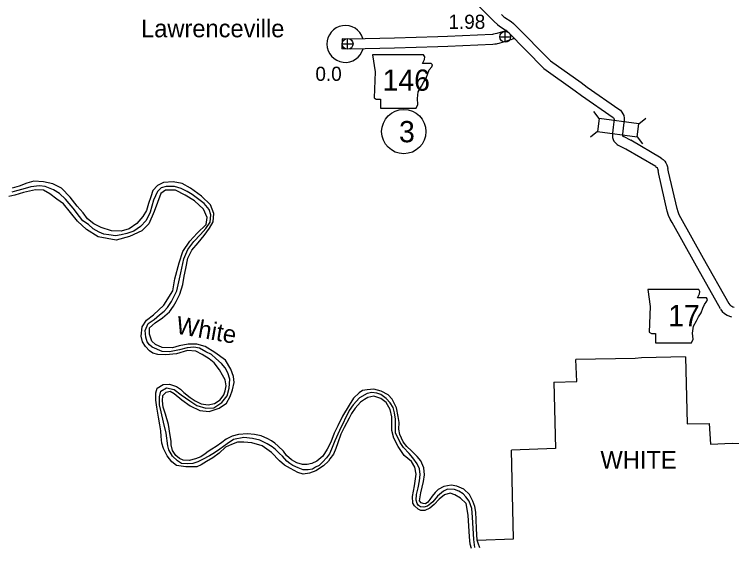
# Model space of a CAD drawing. Extents: x -939622 to -934222, y 1383701 to 1385301.
# Drawn here: x -935986.8 to -935922.6, y 1383989.8 to 1384037.4 of the extents above; entities that cross this region are included whole.
import ezdxf

# ---------------------------------------------------------------- set-up
doc = ezdxf.new("R2010")
doc.units = 0
for name, color, linetype in [('Level 10', 7, 'Continuous'), ('Level 2', 7, 'Continuous'), ('Level 20', 7, 'Continuous'), ('Level 21', 7, 'Continuous'), ('Level 24', 7, 'Continuous'), ('Level 25', 7, 'Continuous'), ('Level 26', 7, 'Continuous'), ('Level 27', 7, 'Continuous'), ('Level 7', 7, 'Continuous'), ('Level 9', 7, 'Continuous')]:
    doc.layers.add(name, color=color, linetype=linetype)

msp = doc.modelspace()

# ---------------------------------------------------------------- linework, layer by layer
at = {"layer": 'Level 10'}
for points in [[(-935954.97, 1384050.035), (-935949.402, 1384043.116), (-935945.476, 1384038.46), (-935943.829, 1384036.81)], [(-935943.19, 1384037.445), (-935942.968, 1384037.219), (-935942.873, 1384037.154), (-935942.317, 1384036.805), (-935942.097, 1384036.629), (-935941.939, 1384036.464)], [(-935943.831, 1384036.812), (-935943.549, 1384036.527), (-935943.368, 1384036.402), (-935942.839, 1384036.07), (-935942.705, 1384035.963), (-935942.589, 1384035.841)], [(-935941.944, 1384036.469), (-935938.802, 1384033.284), (-935936.059, 1384031.336), (-935935.494, 1384030.92)], [(-935942.718, 1384035.997), (-935942.885, 1384035.954), (-935943.605, 1384035.718), (-935943.753, 1384035.7), (-935943.864, 1384035.668), (-935943.893, 1384035.663), (-935943.997, 1384035.656), (-935948.008, 1384035.454), (-935948.884, 1384035.438), (-935952.767, 1384035.325), (-935956.69, 1384035.233), (-935957.434, 1384035.254)], [(-935942.585, 1384035.837), (-935939.388, 1384032.596), (-935936.587, 1384030.606), (-935936.027, 1384030.195)], [(-935942.036, 1384035.267), (-935942.097, 1384035.256), (-935942.126, 1384035.247), (-935942.223, 1384035.211), (-935942.266, 1384035.2), (-935942.329, 1384035.167), (-935942.47, 1384035.131), (-935942.634, 1384035.089), (-935943.411, 1384034.834), (-935943.573, 1384034.815), (-935943.659, 1384034.79), (-935943.786, 1384034.768), (-935943.946, 1384034.758), (-935947.977, 1384034.555), (-935948.863, 1384034.538), (-935952.743, 1384034.425), (-935956.692, 1384034.333), (-935957.46, 1384034.355)], [(-935957.434, 1384035.254), (-935957.46, 1384034.355)], [(-935935.505, 1384030.928), (-935932.665, 1384028.969)], [(-935936.016, 1384030.187), (-935933.176, 1384028.228)], [(-935932.665, 1384028.969), (-935932.533, 1384028.86), (-935932.399, 1384028.703), (-935932.315, 1384028.555), (-935932.232, 1384028.396), (-935932.185, 1384028.165), (-935932.189, 1384027.993)], [(-935933.085, 1384028.062), (-935933.177, 1384027.362), (-935933.242, 1384026.822)], [(-935933.212, 1384028.256), (-935933.171, 1384028.221), (-935933.139, 1384028.183), (-935933.106, 1384028.125), (-935933.089, 1384028.093), (-935933.087, 1384028.083), (-935933.088, 1384028.014)], [(-935932.189, 1384027.993), (-935932.284, 1384027.249), (-935932.348, 1384026.715)], [(-935933.245, 1384026.792), (-935933.253, 1384026.623), (-935933.237, 1384026.436), (-935933.194, 1384026.248), (-935933.108, 1384026.098), (-935933.011, 1384025.966), (-935932.912, 1384025.874), (-935932.812, 1384025.799), (-935932.735, 1384025.751)], [(-935932.346, 1384026.745), (-935932.351, 1384026.638), (-935932.346, 1384026.582), (-935932.335, 1384026.566), (-935932.334, 1384026.565), (-935932.307, 1384026.545), (-935932.266, 1384026.52)], [(-935932.294, 1384026.536), (-935931.6, 1384026.177)], [(-935928.873, 1384024.574), (-935931.6, 1384026.177)], [(-935932.735, 1384025.751), (-935932.013, 1384025.378)], [(-935929.362, 1384023.82), (-935932.034, 1384025.39)], [(-935928.873, 1384024.574), (-935928.716, 1384024.462), (-935928.564, 1384024.316), (-935928.45, 1384024.151), (-935928.367, 1384023.974), (-935928.311, 1384023.797), (-935928.279, 1384023.664)], [(-935929.396, 1384023.842), (-935929.293, 1384023.768), (-935929.254, 1384023.73), (-935929.233, 1384023.701), (-935929.207, 1384023.644), (-935929.178, 1384023.555), (-935929.154, 1384023.454)], [(-935922.795, 1384011.543), (-935925.089, 1384015.606), (-935927.119, 1384019.249), (-935927.256, 1384019.514), (-935927.37, 1384019.77), (-935927.464, 1384020.059), (-935928.211, 1384023.351), (-935928.277, 1384023.654)], [(-935923.579, 1384011.101), (-935925.874, 1384015.166), (-935927.911, 1384018.823), (-935928.067, 1384019.124), (-935928.211, 1384019.447), (-935928.332, 1384019.82), (-935929.089, 1384023.156), (-935929.156, 1384023.463)], [(-935922.811, 1384011.569), (-935922.728, 1384011.442), (-935922.667, 1384011.388), (-935922.563, 1384011.321), (-935922.48, 1384011.288), (-935922.354, 1384011.256)], [(-935923.563, 1384011.075), (-935923.415, 1384010.849), (-935923.214, 1384010.67), (-935922.977, 1384010.517), (-935922.756, 1384010.43), (-935922.574, 1384010.384)]]:
    msp.add_lwpolyline(points, dxfattribs=at)
at = {"layer": 'Level 2'}
for points in [[(-935969.203, 1384019.514), (-935969.342, 1384019.983), (-935969.799, 1384020.511), (-935970.403, 1384020.982), (-935970.878, 1384021.318), (-935971.313, 1384021.605), (-935971.868, 1384021.853), (-935972.438, 1384022.05), (-935973.199, 1384022.051), (-935973.633, 1384021.924), (-935973.976, 1384021.586), (-935974.321, 1384020.824), (-935974.638, 1384019.759), (-935974.982, 1384019.012), (-935975.499, 1384018.452), (-935976.099, 1384018.032), (-935976.725, 1384017.829), (-935977.222, 1384017.713), (-935977.73, 1384017.619), (-935978.324, 1384017.708), (-935978.773, 1384017.782), (-935979.205, 1384017.964), (-935979.737, 1384018.254), (-935980.16, 1384018.647), (-935980.656, 1384018.983), (-935980.957, 1384019.364), (-935981.526, 1384020.108), (-935981.88, 1384020.534), (-935982.217, 1384020.909), (-935982.755, 1384021.419), (-935983.275, 1384021.74), (-935984.033, 1384022.03), (-935984.552, 1384022.115), (-935985.322, 1384022.02), (-935986.037, 1384021.814), (-935986.602, 1384021.65), (-935987.015, 1384021.532)], [(-935952.656, 1383999.955), (-935952.667, 1384000.382), (-935952.657, 1384001.212), (-935952.743, 1384001.781), (-935952.871, 1384002.273), (-935953.13, 1384002.682), (-935953.503, 1384003.063), (-935953.968, 1384003.422), (-935954.331, 1384003.554), (-935954.79, 1384003.598), (-935955.209, 1384003.521), (-935955.887, 1384003.123), (-935956.448, 1384002.49), (-935956.815, 1384002.002), (-935957.684, 1384000.213), (-935958.094, 1383999.295), (-935958.391, 1383998.551), (-935958.563, 1383998.106), (-935958.84, 1383997.759), (-935959.166, 1383997.397), (-935959.506, 1383997.081), (-935959.814, 1383996.912), (-935960.107, 1383996.736), (-935960.475, 1383996.684), (-935960.933, 1383996.701), (-935961.392, 1383996.856), (-935961.845, 1383997.075), (-935962.131, 1383997.26), (-935962.395, 1383997.464), (-935962.786, 1383997.896), (-935963.053, 1383998.151), (-935963.399, 1383998.502), (-935963.7, 1383998.751), (-935964.147, 1383999.003), (-935964.819, 1383999.344), (-935965.481, 1383999.492), (-935966.246, 1383999.569), (-935967.174, 1383999.398), (-935967.732, 1383999.017), (-935968.408, 1383998.546), (-935968.883, 1383998.205), (-935969.328, 1383997.934), (-935969.953, 1383997.598), (-935970.366, 1383997.417), (-935970.806, 1383997.262), (-935971.312, 1383997.21), (-935971.839, 1383997.266), (-935972.17, 1383997.502), (-935972.623, 1383997.916), (-935972.955, 1383998.49), (-935973.052, 1383998.826), (-935973.212, 1383999.975), (-935973.44, 1384000.966), (-935973.653, 1384001.889), (-935973.787, 1384002.511), (-935973.798, 1384003.224), (-935973.677, 1384003.718), (-935973.154, 1384004.02), (-935972.479, 1384003.88), (-935971.864, 1384003.394), (-935971.083, 1384002.858), (-935970.44, 1384002.43), (-935969.652, 1384002.203), (-935968.939, 1384002.223), (-935968.225, 1384002.7), (-935967.75, 1384003.318), (-935967.552, 1384003.992), (-935967.507, 1384004.786), (-935967.686, 1384005.375), (-935967.924, 1384005.819), (-935968.258, 1384006.2), (-935968.745, 1384006.647), (-935969.141, 1384007.004), (-935969.636, 1384007.246), (-935970.228, 1384007.561), (-935970.734, 1384007.662), (-935971.33, 1384007.609), (-935972.003, 1384007.427), (-935972.895, 1384007.244), (-935973.567, 1384007.266), (-935974.455, 1384007.673), (-935974.698, 1384007.874), (-935974.897, 1384008.147), (-935975.018, 1384008.547), (-935975.086, 1384009.142), (-935974.812, 1384009.768), (-935974.275, 1384010.143), (-935973.788, 1384010.544), (-935973.384, 1384010.9), (-935973.08, 1384011.204), (-935972.713, 1384011.75), (-935972.246, 1384012.692), (-935972.055, 1384013.505), (-935971.896, 1384014.329), (-935971.612, 1384015.566), (-935971.259, 1384016.415), (-935970.713, 1384017.117), (-935970.119, 1384017.75), (-935969.642, 1384018.286), (-935969.245, 1384018.838), (-935969.203, 1384019.514)], [(-935945.575, 1383989.725), (-935945.655, 1383990.458), (-935945.782, 1383992.446), (-935945.842, 1383993.236), (-935946.084, 1383993.891), (-935946.373, 1383994.261), (-935946.616, 1383994.531), (-935946.994, 1383994.764), (-935947.393, 1383994.932), (-935948.008, 1383994.963), (-935948.357, 1383994.788), (-935948.898, 1383994.317), (-935949.328, 1383993.814), (-935949.507, 1383993.66), (-935949.791, 1383993.437), (-935950.126, 1383993.34), (-935950.414, 1383993.384), (-935950.597, 1383993.492), (-935950.72, 1383993.678), (-935950.811, 1383993.975), (-935950.78, 1383994.478), (-935950.647, 1383995.071), (-935950.52, 1383995.699), (-935950.451, 1383996.28), (-935950.506, 1383996.77), (-935950.72, 1383997.218), (-935951.103, 1383997.77), (-935951.443, 1383998.148), (-935951.963, 1383998.694), (-935952.246, 1383999.135), (-935952.472, 1383999.592), (-935952.656, 1383999.955)]]:
    msp.add_lwpolyline(points, dxfattribs=at)
at = {"layer": 'Level 20'}
for p, q in [((-935934.42, 1384028.128), (-935934.901, 1384028.756)), ((-935930.886, 1384027.661), (-935930.258, 1384028.143)), ((-935934.575, 1384026.95), (-935935.204, 1384026.468)), ((-935931.042, 1384026.483), (-935930.56, 1384025.855))]:
    msp.add_line(p, q, dxfattribs=at)
msp.add_lwpolyline([(-935930.886, 1384027.661), (-935934.42, 1384028.128), (-935934.575, 1384026.95), (-935931.042, 1384026.483)], close=True, dxfattribs=at)
at = {"layer": 'Level 21'}
for points in [[(-935954.714, 1384033.822), (-935954.486, 1384032.299), (-935954.588, 1384029.99), (-935954.384, 1384029.863), (-935954.004, 1384029.863), (-935954.004, 1384029.051), (-935950.806, 1384029.051), (-935950.654, 1384029.381), (-935950.705, 1384029.914), (-935950.629, 1384030.523), (-935950.35, 1384031.005), (-935950.172, 1384031.361), (-935949.918, 1384031.741), (-935949.766, 1384032.147), (-935949.639, 1384032.477), (-935949.411, 1384032.756), (-935949.36, 1384032.934), (-935949.461, 1384033.061), (-935950.248, 1384033.061), (-935950.07, 1384033.416), (-935950.045, 1384033.644), (-935950.15, 1384033.82)], [(-935930.088, 1384012.832), (-935929.859, 1384011.309), (-935929.961, 1384009), (-935929.758, 1384008.873), (-935929.377, 1384008.873), (-935929.377, 1384008.061), (-935926.18, 1384008.061), (-935926.028, 1384008.391), (-935926.078, 1384008.924), (-935926.002, 1384009.533), (-935925.723, 1384010.015), (-935925.545, 1384010.37), (-935925.292, 1384010.751), (-935925.139, 1384011.157), (-935925.012, 1384011.487), (-935924.784, 1384011.766), (-935924.733, 1384011.944), (-935924.835, 1384012.071), (-935925.622, 1384012.071), (-935925.444, 1384012.426), (-935925.419, 1384012.654), (-935925.524, 1384012.83)]]:
    msp.add_lwpolyline(points, close=True, dxfattribs=at)
at = {"layer": 'Level 24'}
msp.add_arc((-935957.157, 1384034.797), 1.65, 17.41887, 344.76747, dxfattribs=at)
at = {"layer": 'Level 26'}
for p, q in [((-935942.847, 1384034.946), (-935942.847, 1384035.921)), ((-935956.953, 1384034.319), (-935956.953, 1384035.294)), ((-935943.335, 1384035.434), (-935942.36, 1384035.434)), ((-935957.441, 1384034.806), (-935956.466, 1384034.806))]:
    msp.add_line(p, q, dxfattribs=at)
for centre in [(-935942.847, 1384035.434), (-935956.953, 1384034.806)]:
    msp.add_circle(centre, 0.487, dxfattribs=at)
at = {"layer": 'Level 27'}
msp.add_circle((-935951.927, 1384026.95), 1.98, dxfattribs=at)
at = {"layer": 'Level 7'}
for points in [[(-935926.715, 1384006.802), (-935930.656, 1384006.695), (-935931.214, 1384006.658)], [(-935926.715, 1384006.802), (-935926.558, 1384000.8), (-935924.586, 1384000.846)], [(-935938.477, 1384004.526), (-935936.437, 1384004.59), (-935936.536, 1384006.546)], [(-935931.214, 1384006.658), (-935936.536, 1384006.546)], [(-935938.477, 1384004.526), (-935938.339, 1383998.586)], [(-935924.586, 1384000.846), (-935924.477, 1383998.989), (-935922.526, 1383999.065), (-935920.519, 1383998.99), (-935920.455, 1383997.019)], [(-935945.362, 1383990.408), (-935942.097, 1383990.503), (-935942.278, 1383998.457)], [(-935938.339, 1383998.586), (-935942.278, 1383998.457)]]:
    msp.add_lwpolyline(points, dxfattribs=at)
at = {"layer": 'Level 9'}
for points in [[(-935971.765, 1384022.296), (-935972.586, 1384022.447), (-935973.445, 1384022.385), (-935973.975, 1384022.134), (-935974.381, 1384021.684), (-935974.579, 1384021.125), (-935974.766, 1384020.526), (-935974.947, 1384019.9), (-935975.289, 1384019.351), (-935975.817, 1384018.725), (-935976.501, 1384018.242), (-935977.238, 1384018.05), (-935978.088, 1384018.063), (-935979.018, 1384018.367), (-935979.666, 1384018.712), (-935980.243, 1384019.146), (-935980.637, 1384019.671), (-935981.179, 1384020.272), (-935981.799, 1384021.082), (-935982.562, 1384021.898), (-935983.354, 1384022.278), (-935984.179, 1384022.471), (-935985.045, 1384022.511), (-935985.682, 1384022.341), (-935986.349, 1384022.072), (-935986.984, 1384021.89)], [(-935952.425, 1384001.448), (-935952.568, 1384002.223), (-935952.963, 1384002.998), (-935953.312, 1384003.397), (-935953.957, 1384003.723), (-935954.614, 1384003.914), (-935955.195, 1384003.855), (-935955.611, 1384003.773), (-935955.916, 1384003.571), (-935956.426, 1384003.1), (-935956.823, 1384002.474), (-935957.424, 1384001.504), (-935957.844, 1384000.631), (-935958.165, 1383999.959), (-935958.468, 1383999.149), (-935958.783, 1383998.529), (-935959.173, 1383997.897), (-935959.705, 1383997.459), (-935960.145, 1383997.244), (-935960.567, 1383997.159), (-935960.998, 1383997.164), (-935961.514, 1383997.307), (-935961.97, 1383997.577), (-935962.424, 1383997.963), (-935962.683, 1383998.36), (-935963.167, 1383998.819), (-935963.476, 1383999.07), (-935963.755, 1383999.292), (-935964.106, 1383999.475), (-935964.694, 1383999.732), (-935965.282, 1383999.86), (-935965.908, 1383999.909), (-935966.711, 1383999.859), (-935967.303, 1383999.686), (-935967.812, 1383999.42), (-935968.212, 1383999.127), (-935968.726, 1383998.762), (-935969.097, 1383998.539), (-935969.45, 1383998.327), (-935969.721, 1383998.113), (-935970.107, 1383997.853), (-935970.585, 1383997.657), (-935971.133, 1383997.52), (-935971.669, 1383997.543), (-935972.006, 1383997.698), (-935972.327, 1383997.98), (-935972.616, 1383998.427), (-935972.741, 1383998.914), (-935972.76, 1383999.26), (-935972.836, 1383999.765), (-935972.981, 1384000.739), (-935973.259, 1384001.659), (-935973.453, 1384002.305), (-935973.527, 1384002.864), (-935973.511, 1384003.324), (-935973.203, 1384003.65), (-935972.853, 1384003.741), (-935972.49, 1384003.513), (-935971.808, 1384002.961), (-935971.063, 1384002.401), (-935970.172, 1384002.009), (-935969.348, 1384001.9), (-935968.457, 1384002.206), (-935967.796, 1384002.641), (-935967.46, 1384003.246), (-935967.246, 1384003.842), (-935967.113, 1384004.489), (-935967.169, 1384005.03), (-935967.402, 1384005.7), (-935967.884, 1384006.499), (-935968.83, 1384007.188), (-935969.71, 1384007.736), (-935970.457, 1384007.939), (-935971.235, 1384007.937), (-935972.023, 1384007.776), (-935972.63, 1384007.618), (-935973.553, 1384007.636), (-935974.15, 1384007.893), (-935974.478, 1384008.211), (-935974.683, 1384008.833), (-935974.688, 1384009.396), (-935974.193, 1384009.851), (-935973.514, 1384010.283), (-935972.905, 1384010.838), (-935972.544, 1384011.323), (-935972.294, 1384011.751), (-935971.961, 1384012.407), (-935971.694, 1384013.277), (-935971.592, 1384014.008), (-935971.448, 1384014.709), (-935971.271, 1384015.642), (-935970.896, 1384016.358), (-935970.344, 1384017.012), (-935969.792, 1384017.663), (-935969.306, 1384018.311), (-935969, 1384018.874), (-935968.945, 1384019.611), (-935969.233, 1384020.386), (-935970.044, 1384021.178), (-935971.008, 1384021.886), (-935971.765, 1384022.296)], [(-935969.622, 1384018.629), (-935969.516, 1384019.27), (-935969.846, 1384020.018), (-935970.675, 1384020.756), (-935971.509, 1384021.28), (-935972.362, 1384021.723), (-935973.266, 1384021.702), (-935973.688, 1384021.416), (-935974.269, 1384019.808), (-935974.739, 1384018.7), (-935975.372, 1384018.076), (-935976.481, 1384017.568), (-935977.666, 1384017.249), (-935979.276, 1384017.546), (-935980.345, 1384018.205), (-935981.138, 1384018.948), (-935982.378, 1384020.482), (-935982.975, 1384020.904), (-935983.615, 1384021.378), (-935984.182, 1384021.704), (-935984.889, 1384021.736), (-935985.985, 1384021.504), (-935986.742, 1384021.259), (-935987.296, 1384021.152)], [(-935950.831, 1383996.3), (-935950.929, 1383996.928), (-935951.227, 1383997.424), (-935951.903, 1383997.984), (-935952.424, 1383998.786), (-935952.825, 1383999.531), (-935952.993, 1384000.216), (-935952.986, 1384000.902), (-935952.994, 1384001.428), (-935953.143, 1384002.08), (-935953.498, 1384002.72), (-935953.988, 1384003.082), (-935954.606, 1384003.267), (-935955.13, 1384003.161), (-935955.449, 1384002.973), (-935955.796, 1384002.75), (-935956.283, 1384002.216), (-935956.595, 1384001.741), (-935956.828, 1384001.301), (-935957.265, 1384000.482), (-935957.548, 1383999.871), (-935957.841, 1383999.109), (-935958.022, 1383998.594), (-935958.227, 1383998.076), (-935958.534, 1383997.664), (-935958.663, 1383997.477), (-935959.101, 1383997.04), (-935959.786, 1383996.59), (-935960.351, 1383996.384), (-935960.944, 1383996.304), (-935961.406, 1383996.453), (-935962.063, 1383996.794), (-935962.597, 1383997.097), (-935963.048, 1383997.502), (-935963.773, 1383998.243), (-935964.592, 1383998.827), (-935965.534, 1383999.107), (-935966.244, 1383999.15), (-935966.81, 1383999.17), (-935967.346, 1383998.952), (-935967.872, 1383998.716), (-935968.46, 1383998.188), (-935969.013, 1383997.772), (-935969.59, 1383997.419), (-935970.068, 1383997.132), (-935970.457, 1383996.968), (-935971.428, 1383996.966), (-935972.258, 1383997.066), (-935972.697, 1383997.417), (-935973.094, 1383997.942), (-935973.426, 1383998.606), (-935973.574, 1383999.087), (-935973.636, 1383999.664), (-935973.668, 1384000.175), (-935973.753, 1384000.719), (-935973.894, 1384001.386), (-935974.047, 1384002.291), (-935974.124, 1384002.913), (-935974.126, 1384003.572), (-935973.996, 1384004.005), (-935973.469, 1384004.314), (-935972.888, 1384004.339), (-935972.28, 1384004.136), (-935971.904, 1384003.891), (-935971.604, 1384003.612), (-935971.063, 1384003.153), (-935970.592, 1384002.853), (-935970.055, 1384002.599), (-935969.434, 1384002.507), (-935968.874, 1384002.611), (-935968.375, 1384002.961), (-935968.041, 1384003.407), (-935967.92, 1384003.768), (-935967.84, 1384004.196), (-935967.923, 1384004.755), (-935968.14, 1384005.151), (-935968.43, 1384005.641), (-935968.908, 1384006.25), (-935969.359, 1384006.631), (-935969.986, 1384007.011), (-935970.532, 1384007.298), (-935971.278, 1384007.375), (-935972.281, 1384007.071), (-935973.227, 1384006.988), (-935973.949, 1384006.995), (-935974.402, 1384007.138), (-935974.681, 1384007.345), (-935975.063, 1384007.723), (-935975.316, 1384008.134), (-935975.444, 1384008.663), (-935975.339, 1384009.478), (-935974.963, 1384010.075), (-935974.336, 1384010.57), (-935973.395, 1384011.414), (-935972.591, 1384012.703), (-935972.436, 1384013.777), (-935972.022, 1384015.225), (-935971.716, 1384016.215), (-935971.067, 1384017.161), (-935970.431, 1384017.857), (-935969.622, 1384018.629)], [(-935945.129, 1383989.705), (-935945.253, 1383990.119), (-935945.362, 1383990.408), (-935945.413, 1383991.421), (-935945.434, 1383992.251), (-935945.475, 1383992.904), (-935945.576, 1383993.4), (-935945.742, 1383993.895), (-935946.044, 1383994.466), (-935946.561, 1383994.946), (-935947.161, 1383995.227), (-935947.697, 1383995.322), (-935948.341, 1383995.194), (-935948.861, 1383994.919), (-935949.13, 1383994.668), (-935949.371, 1383994.325), (-935949.598, 1383994.021), (-935949.762, 1383993.792), (-935949.995, 1383993.641), (-935950.196, 1383993.664), (-935950.373, 1383993.724), (-935950.508, 1383993.928), (-935950.412, 1383994.641), (-935950.17, 1383995.64), (-935950.082, 1383996.242), (-935950.123, 1383996.864), (-935950.392, 1383997.492), (-935950.729, 1383997.888), (-935951.249, 1383998.398), (-935951.637, 1383998.779), (-935951.991, 1383999.196), (-935952.281, 1383999.848), (-935952.367, 1384000.341), (-935952.342, 1384000.924), (-935952.425, 1384001.448)], [(-935945.859, 1383989.643), (-935945.986, 1383990.021), (-935946.046, 1383990.683), (-935946.151, 1383992.622), (-935946.344, 1383993.68), (-935946.848, 1383994.151), (-935947.359, 1383994.463), (-935947.764, 1383994.585), (-935948.266, 1383994.457), (-935948.753, 1383994.065), (-935949.195, 1383993.595), (-935949.592, 1383993.245), (-935950.038, 1383993.036), (-935950.397, 1383993.047), (-935950.646, 1383993.167), (-935950.977, 1383993.476), (-935951.113, 1383993.719), (-935951.151, 1383994.314), (-935950.962, 1383995.262), (-935950.831, 1383996.3)]]:
    msp.add_lwpolyline(points, dxfattribs=at)

# ---------------------------------------------------------------- texts
at = {"layer": 'Level 21'}
for s, p in [('146', (-935953.824, 1384030.609)), ('17', (-935928.253, 1384009.542))]:
    msp.add_text(s, height=1.9008, dxfattribs=at).set_placement(p)
at = {"layer": 'Level 24'}
msp.add_text('Lawrenceville', height=1.584, dxfattribs=at).set_placement((-935975.445, 1384035.393))
at = {"layer": 'Level 25'}
for s, p in [('1.98', (-935947.927, 1384036.149)), ('0.0', (-935959.837, 1384031.494))]:
    msp.add_text(s, height=1.2672, dxfattribs=at).set_placement(p)
at = {"layer": 'Level 27'}
msp.add_text('3', height=1.901, dxfattribs=at).set_placement((-935952.352, 1384025.999))
at = {"layer": 'Level 7'}
msp.add_text('WHITE', height=1.584, dxfattribs=at).set_placement((-935934.319, 1383996.795))
at = {"layer": 'Level 9'}
msp.add_text('White', height=1.584, rotation=350, dxfattribs=at).set_placement((-935972.395, 1384008.897))

doc.saveas('drawing.dxf')
